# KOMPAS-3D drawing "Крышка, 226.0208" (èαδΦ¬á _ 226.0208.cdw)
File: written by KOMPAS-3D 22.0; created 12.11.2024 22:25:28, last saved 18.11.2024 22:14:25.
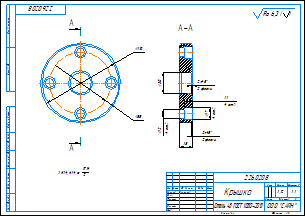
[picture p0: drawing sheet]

Sheet 1: A3, landscape

Document properties: Автор: aleksander.larionov.10@gmail.com; Знак неуказанной шероховатости: 4; Параметр неуказанной шероховатости: Ra 6,3; Масса: 1.120135; Полное имя файла: Крышка _ 226.0208.m3d

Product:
- Part/product: Крышка  | designation 226.0208
    Материал: Сталь 45 ГОСТ 1050-2013 (density 7810 kg/m3)
    Масса: 1.120135

Title block, sheet 1: Наименование: Крышка; designation: 226.0208; Материал: Сталь 45 ГОСТ 1050-2013; Масса: 1,12; Количество листов документа: 1; organisation: ООО "САЙН"; Форматы листов документа: A3; stored path: C:\Мои папки\Работа\Крышки, фланцы\226.0208\Крышка _ 226.0208.cdw; Разработал: Ларионов

Views: Вид 1, Сверху, Разрез А-А
Referenced files in C:\Мои папки\Работа\Крышки, фланцы\226.0208\: Крышка _ 226.0208.m3d
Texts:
  Ra 6,3
  Ra 6,3 ( )
Dimensions and other numbers on the sheet: 110; 85; 226.0208; 18; 2; 2 фаски; 17; 4 отв.; 12; 11; 30; 1 H14, h14,    IT14 2 .; 1:1; 1; 1,12; 226.0208 Крышка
